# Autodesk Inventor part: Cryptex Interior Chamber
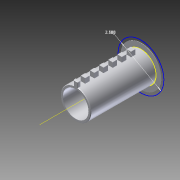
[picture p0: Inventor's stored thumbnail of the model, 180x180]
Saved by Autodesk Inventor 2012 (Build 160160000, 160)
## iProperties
Created: 2012-04
Part Number: Cryptex Interior Chamber
Material: ABS Plastic
Document SubType Name: Modeling
Designer: Pierce
Density: 1.06 g/cm^3
Mass: 46.2804 g
Surface Area: 275.981 cm^2
Volume: 43.6608 cm^3
Author: Pierce
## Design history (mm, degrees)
sketch "Sketch1"
  geometry: C1 r 17.78 at (0, 0); C2 r 20.955 at (0, 0); 1 further point
  constraints: 2 centre point, 1 coincident
  dimensions: "d1" = 3.175 radial gap between concentric circles of C1 C2; "d38" = 41.91 diameter of C2
extrude "Extrusion1" new body sketch "Sketch1" distance "d2" = 90.17; taper "d3" = 0 deg
workaxis "Work Axis1"
sketch "Sketch5"
  geometry: C1 r 20.955 at (0, 0) reference; C2 r 31.75 at (0, 0)
  constraints: 1 centre point, 1 coincident
  dimensions: "d10" = 63.5 diameter of C2
workplane "Work Plane5"
sketch "Sketch7"
  geometry: L1 (25.4, 0)-(-25.4, 0); 2 further points
  constraints: 2 end point, 1 midpoint
  dimensions: "d13" = 7.62 distance from line of L1 point (0, -7.62)
sketch "Sketch6"
  geometry: C1 r 28.067 at (0, 0); C2 r 28.067 at (0, 0)
  constraints: 2 centre point, 1 coincident, 1 concentric
  dimensions: "d59" = 56.134 diameter of C1
loft "Loft1" sketch "Sketch7", "Sketch6" dims "d16" = 10, "d60" = 90 deg, "d61" = 10, "d62" = 90 deg
workplane "Work Plane2"
sketch "Sketch8"
  geometry: L1 (0, -22.225)-(0, 22.225); L2 (-3.175, -21.997)-(-3.175, 21.997); L3 (3.175, -21.997)-(3.175, 21.997); L4 (3.175, -21.997)-(3.175, 21.997); A1 r 22.225 centre (0, 0) between (0, -22.225) and (0, 22.225); A2 r 22.225 centre (0, 0) between (3.175, -21.997) and (3.175, 21.997); 1 further point
  constraints: 8 end point, 6 point on circle, 2 centre point, 2 symmetric about line, 1 coincident, 1 collinear, 1 concentric, 1 midpoint, 1 parallel, 1 vertical
  dimensions: "d19" = 44.45 diameter of A1; "d20" = 6.35 diameter of L2 L1
extrude "Extrusion3" cut sketch "Sketch8" distance "d21" = 48.26; taper "d22" = 0 deg
fillet "Fillet1" dims "d23" = 3.175
fillet "Fillet2" dims "d24" = 1.905
fillet "Fillet3" dims "d25" = 1.5875
workplane "Work Plane4"
sketch "Sketch11" dims "d49" = 25.4
  geometry: L1 (0, 4.897)-(0, 95.916); L2 (-20.955, 90.17)-(20.955, 90.17) reference; L3 (-3.048, 90.17)-(3.048, 90.17); L4 (3.048, 90.17)-(3.048, 86.868); L5 (3.048, 86.868)-(-3.048, 86.868); L6 (-3.048, 86.868)-(-3.048, 90.17); L7 (-3.048, 80.137)-(3.048, 80.137); L8 (3.048, 80.137)-(3.048, 74.041); L9 (3.048, 74.041)-(-3.048, 74.041); L10 (-3.048, 74.041)-(-3.048, 80.137); L11 (-3.048, 67.437)-(3.048, 67.437); L12 (3.048, 67.437)-(3.048, 61.341); L13 (3.048, 61.341)-(-3.048, 61.341); L14 (-3.048, 61.341)-(-3.048, 67.437); L15 (-3.048, 54.737)-(3.048, 54.737); L16 (3.048, 54.737)-(3.048, 48.641); L17 (3.048, 48.641)-(-3.048, 48.641); L18 (-3.048, 48.641)-(-3.048, 54.737); L19 (-3.048, 42.037)-(3.048, 42.037); L20 (3.048, 42.037)-(3.048, 35.941); L21 (3.048, 35.941)-(-3.048, 35.941); L22 (-3.048, 35.941)-(-3.048, 42.037); L23 (-3.048, 29.337)-(3.048, 29.337); L24 (3.048, 29.337)-(3.048, 23.241); L25 (3.048, 23.241)-(-3.048, 23.241); L26 (-3.048, 23.241)-(-3.048, 29.337); L27 (-3.048, 16.637)-(3.048, 16.637); L28 (3.048, 16.637)-(3.048, 10.541); L29 (3.048, 10.541)-(-3.048, 10.541); L30 (-3.048, 10.541)-(-3.048, 16.637); 5 further points
  constraints: 58 end point, 4 parallel, 3 point on line, 2 horizontal, 2 perpendicular, 2 vertical, 1 collinear, 1 midpoint, 40 other
  dimensions: "d40" = 3.302 distance of L5.end L3.start; "d41" = 6.096 distance of L4.end L5.end; "d42" = 6.096 distance of L9.end L7.start; "d43" = 10.033 distance of L7.start L3.start; "d46" = 12.7 distance of L7.start L11.start; "d53" = 6.096 distance of L7.start L7.end
extrude "Extrusion5" join sketch "Sketch11" stored distance "d51" = 25.4; taper "d52" = 0 deg
chamfer "Chamfer1" distance "d56" = 0.635; stored, may be unused: second distance "d57" = 3.175, angle "d58" = 45 deg
body "Solid1"
node "Projected Loop1"
other parameters: "d39" = 27.432
